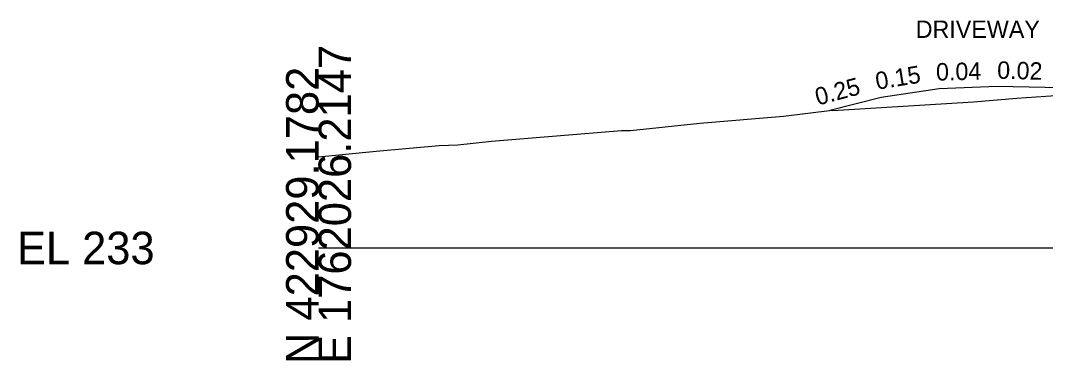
# Model space of a CAD drawing. Extents: x -26 to 3203, y -11010 to 4024.
# Drawn here: x -25.7 to 62.7, y -3509.7 to -3480.4 of the extents above; entities that cross this region are included whole.
import ezdxf

# ---------------------------------------------------------------- set-up
doc = ezdxf.new("R2010")
doc.units = 0
for name, color, linetype in [('Default', 7, 'Continuous'), ('Exist Cross Section Cell', 7, 'Continuous'), ('Exist XS Ground Line', 7, 'Continuous'), ('Prop CMT Conc Surface', 7, 'Continuous'), ('Prop XS SE Text', 7, 'Continuous'), ('Scratch_Level_0', 7, 'Continuous')]:
    doc.layers.add(name, color=color, linetype=linetype)

msp = doc.modelspace()

# ---------------------------------------------------------------- linework, layer by layer
at = {"layer": 'Exist Cross Section Cell'}
msp.add_line((0, -3500), (100, -3500), dxfattribs=at)
at = {"layer": 'Exist XS Ground Line'}
msp.add_lwpolyline([(0, -3492.142), (4.961, -3491.658), (10.406, -3491.182), (11.995, -3491.129), (14.901, -3490.802), (26.127, -3489.876), (26.883, -3489.871), (32.855, -3489.241), (40.088, -3488.636), (44.279, -3488.133), (44.336, -3488.156), (44.796, -3488.121), (56.45, -3487.402), (60.197, -3487.096), (64.359, -3486.807)], dxfattribs=at)
msp.add_lwpolyline([(0, -3492.142), (4.961, -3491.658), (10.406, -3491.182), (11.995, -3491.129), (14.901, -3490.802), (26.127, -3489.876), (26.883, -3489.871), (32.855, -3489.241), (40.088, -3488.636), (44.279, -3488.133), (44.336, -3488.156), (44.796, -3488.121), (56.45, -3487.402), (60.197, -3487.096), (64.359, -3486.807)], dxfattribs=at)
msp.add_lwpolyline([(0, -3492.142), (4.961, -3491.658), (10.406, -3491.182), (11.995, -3491.129), (14.901, -3490.802), (26.127, -3489.876), (26.883, -3489.871), (32.855, -3489.241), (40.088, -3488.636), (44.279, -3488.133), (44.336, -3488.156), (44.796, -3488.121), (56.45, -3487.402), (60.197, -3487.096), (64.359, -3486.807)], dxfattribs=at)
msp.add_lwpolyline([(0, -3492.142), (4.961, -3491.658), (10.406, -3491.182), (11.995, -3491.129), (14.901, -3490.802), (26.127, -3489.876), (26.883, -3489.871), (32.855, -3489.241), (40.088, -3488.636), (44.279, -3488.133), (44.336, -3488.156), (44.796, -3488.121), (56.45, -3487.402), (60.197, -3487.096), (64.359, -3486.807)], dxfattribs=at)
msp.add_lwpolyline([(0, -3492.142), (4.961, -3491.658), (10.406, -3491.182), (11.995, -3491.129), (14.901, -3490.802), (26.127, -3489.876), (26.883, -3489.871), (32.855, -3489.241), (40.088, -3488.636), (44.279, -3488.133), (44.336, -3488.156), (44.796, -3488.121), (56.45, -3487.402), (60.197, -3487.096), (64.359, -3486.807)], dxfattribs=at)
at = {"layer": 'Prop CMT Conc Surface'}
for points in [[(58.499, -3486.1), (53.499, -3486.3), (48.499, -3487.05), (44.064, -3488.159)], [(66, -3486.33), (63.999, -3486.21), (58.499, -3486.1)]]:
    msp.add_lwpolyline(points, dxfattribs=at)

# ---------------------------------------------------------------- texts
at = {"layer": 'Default'}
msp.add_text('-', height=0.0001, dxfattribs=at).set_placement((0, -3500))
at = {"layer": 'Exist Cross Section Cell'}
for s, p in [('E 1762026.2147', (2.8, -3510)), ('N 422929.1782', (0, -3510))]:
    msp.add_text(s, height=2.8, rotation=90, dxfattribs=at).set_placement(p)
msp.add_text('EL 233', height=2.8, dxfattribs=at).set_placement((-26, -3501.4))
at = {"layer": 'Prop XS SE Text'}
for s, rotation, p in [('DRIVEWAY', 360, (51.475, -3481.912)), ('0.15', 9.28104, (48.132, -3486.38)), ('0.04', 1.14576, (53.238, -3485.586)), ('0.02', 358.51472, (58.48, -3485.42)), ('0.25', 14.94695, (43.033, -3487.743))]:
    msp.add_text(s, height=1.5, rotation=rotation, dxfattribs=at).set_placement(p)
at = {"layer": 'Scratch_Level_0'}
for s, p in [('LT_SS_Fill_1BrkPnt', (53.499, -3486.381)), ('LT_GS_OS_CTL', (58.499, -3486.168)), ('LT_SS_Fill_2BrkPnt', (48.499, -3487.132)), ('Exterior Boundary', (44.064, -3488.239)), ('LT_Slope_Fill', (44.064, -3488.216)), ('LT_SS_Fill', (44.064, -3488.201))]:
    msp.add_text(s, height=0.015, rotation=90, dxfattribs=at).set_placement(p)

doc.saveas('drawing.dxf')
